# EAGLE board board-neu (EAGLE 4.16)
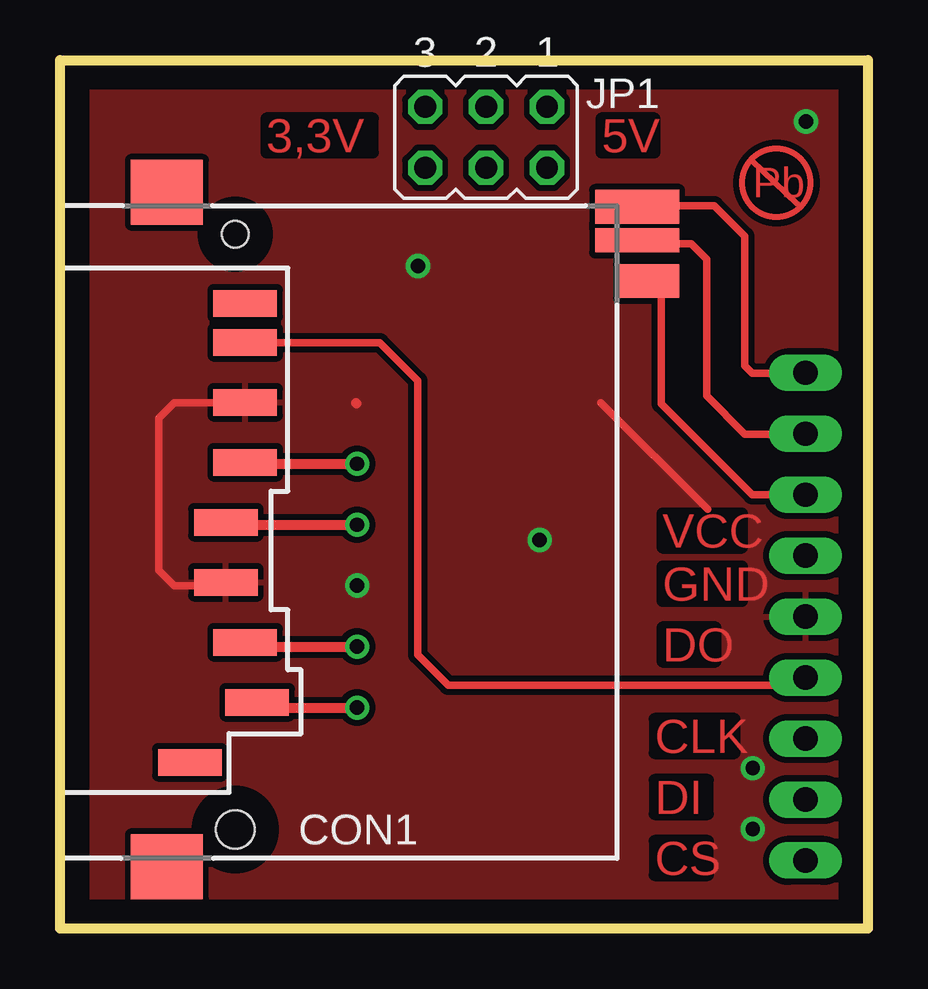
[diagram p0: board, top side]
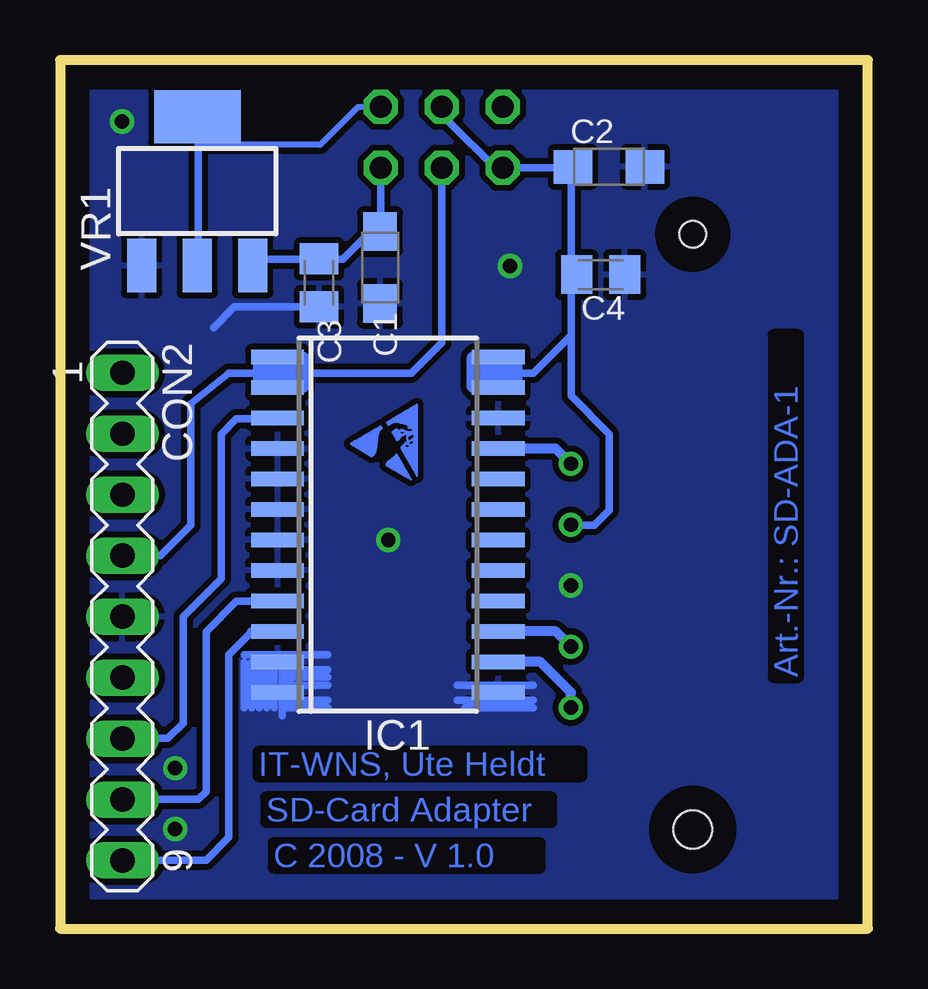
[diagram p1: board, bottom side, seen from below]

Size 33.66 x 36.19 mm. Coordinates in mm from the lower left corner, seen from the top.
Outline: 0,0 0,36.19 33.66,36.19 33.66,0 0,0
Copper layers (1*16): Top 0.035mm / dielectric 1.5mm / Bottom 0.035mm
Design rules "default": minimum track width 10mil, minimum drill 24mil, track to track 8mil, track to pad 8mil, pad to pad 8mil, via to via 8mil, smd to smd 8mil, copper to edge 40mil, drill to drill 8mil, minimum pad ring 10mil, minimum via ring 8mil, stop-mask expansion 4mil, vias tented up to drill 0mil, thermal gap 10mil
Milling: 4 lines

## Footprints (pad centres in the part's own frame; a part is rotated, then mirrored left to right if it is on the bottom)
SMC_A = smd 1.6 x 1.4: + -1.5,0; - 1.5,0
C0805K = smd 1.3 x 1.6: 1 -1,0; 2 1,0
FPS009-3000 = smd 2.65 x 1.1: 1 -0.915,-5.3; 2 -0.415,-7.8; 3 0.385,-10.3; 4 0.385,-12.8; 5 -0.415,-15.3; 6 -0.415,-17.8; 7 -0.415,-20.3; 8 -0.415,-21.925; 9 1.885,-2.8 | smd 3.5 x 1: COM_TERM -16.75,-24.55 | smd 2.5 x 1.4: DETECT -17.25,-22.85 | smd 3 x 2.7: M1 2.85,1.55; M2 2.85,-26.55 | smd 3.5 x 1.4: WRITE_PROT -16.75,-25.95 | hole 1.6: 0,0 | hole 1.1: 0,-24.8
MA09-1 = drill 1.016 long: 1 -10.16,0; 2 -7.62,0; 3 -5.08,0; 4 -2.54,0; 5 0,0; 6 2.54,0; 7 5.08,0; 8 7.62,0; 9 10.16,0
SO24 = smd 0.6 x 2.2: 1 -6.985,-4.6; 2 -5.715,-4.6; 3 -4.445,-4.6; 4 -3.175,-4.6; 5 -1.905,-4.6; 6 -0.635,-4.6; 7 0.635,-4.6; 8 1.905,-4.6; 9 3.175,-4.6; 10 4.445,-4.6; 11 5.715,-4.6; 12 6.985,-4.6; 13 6.985,4.6; 14 5.715,4.6; 15 4.445,4.6; 16 3.175,4.6; 17 1.905,4.6; 18 0.635,4.6; 19 -0.635,4.6; 20 -1.905,4.6; 21 -3.175,4.6; 22 -4.445,4.6; 23 -5.715,4.6; 24 -6.985,4.6
JP3Q = drill 0.914 octagon: 1 -2.54,-1.27; 2 -2.54,1.27; 3 0,-1.27; 4 0,1.27; 5 2.54,-1.27; 6 2.54,1.27
SOT-233 = smd 1.219 x 2.235: 1 -2.311,-3.099; 2 0,-3.099; 3 2.311,-3.099 | smd 3.6 x 2.2: 4 0,3.099

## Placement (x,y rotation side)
C1  10µF  [SMC_A]  20.33,27.54 270 bottom
C2  10µF  [SMC_A]  10.79,31.74 0 bottom
C3  100nF  [C0805K]  22.87,26.91 270 bottom
C4  100nF  [C0805K]  11.13,27.25 180 bottom
CON1  [FPS009-3000]  7.3,4.13 180 top
CON2  [MA09-1]  31.07,13 270 bottom
E$2  [GEH1]  21.88,22.15 270 top
IC1  74LVC4245  [SO24]  20,16.83 270 bottom
JP1  [JP3Q]  17.75,32.97 180 top
VR1  LM1117-3.3  [SOT-233]  27.94,30.73 0 bottom

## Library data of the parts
C1-C4 = rcl
CON1 = con-yamaichi
CON2 = con-lstb
E$2 = layout_s65
IC1 = micro-philips
JP1 = jumper
VR1 = LM1117

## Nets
GND: C1.- C2.- C3.2 C4.1 CON1.3 CON1.6 CON2.5 IC1.4 IC1.5 IC1.6 IC1.7 IC1.8 IC1.11 IC1.12 IC1.13 IC1.22 VR1.1

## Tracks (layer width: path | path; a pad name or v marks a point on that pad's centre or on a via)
GND  (via drill 0.6)
  Top 0.305: 6.66,21.91 4.76,21.91 4.12,21.27 4.12,14.92 4.76,14.29 6.03,14.29 | 26.98,17.46 22.54,21.91
  Top 0.406: 12.36,21.87 12.33,21.91
  Bottom 0.305: 13.95,9.19 16.8,9.19 | 13.95,10.14 17.12,10.14 | 15.22,9.51 15.85,9.51 | 15.22,9.51 13.95,9.51 | 15.22,9.51 17.12,9.51 | 24.41,10.78 24.41,11.1 | 24.41,10.78 22.51,10.78 | 24.41,10.46 24.41,10.78 | 24.41,10.46 22.51,10.46 | 24.41,10.14 24.41,10.46 | 24.41,10.14 22.51,10.14 | 24.41,9.51 24.41,10.14 | 24.41,9.51 22.51,9.51 | 24.41,9.19 24.41,8.88 | 24.41,9.19 24.41,9.51 | 22.51,9.19 24.41,9.19 | 22.51,11.41 25.99,11.41 | 24.09,9.19 24.09,11.1 | 24.73,9.19 24.73,11.1 | 25.04,9.19 25.04,11.1 | 25.36,9.19 25.36,11.1 | 25.99,9.19 25.99,11.1 | 25.68,9.19 25.68,11.1 | C3.2 26.39,25.91 27.26,25.04
  other vias: 12.38,14.29 19.99,16.19 14.91,27.61 31.08,33.63 28.86,6.68 28.86,4.15
  pour Top (isolate 0.254): 0.95,-0.32 0.63,36.19 33.66,35.87 33.66,-0.64
  pour Bottom (isolate 0.254): 0.31,36.19 0,-0.01 33.67,-0.01 33.66,36.19
S$1
  Top 0.305: 7.92,24.41 13.31,24.41 14.9,22.82 14.9,11.41 16.17,10.14 31.07,10.14
S$2
  Top 0.305: 25.04,26.63 25.04,21.87 28.85,18.07 31.07,18.07
S$3
  Bottom 0.305: 25.08,13.65 25.71,13.65
S$4
  Bottom 0.305: 23.49,22.54 23.46,22.51 23.77,22.51 23.81,22.54 23.84,22.51 24.09,22.51 24.13,22.54 | 24.13,23.81 24.16,23.77 24.41,23.77 24.41,23.78 24.44,23.81
  Bottom 0.406: 23.49,22.54 23.49,23.81 | 23.81,22.54 23.81,23.81 | 24.13,23.81 24.13,22.54 | 24.44,22.54 24.44,23.81 24.76,23.81 | 24.76,23.81 24.76,22.54 | 25.08,23.81 24.76,23.81 | 25.08,23.81 25.08,22.54 | 25.08,23.81 25.39,23.81 25.39,22.54
S$5
  Top 0.305: 25.36,28.53 26.31,28.53 26.95,27.9 26.95,22.19 28.53,20.61 31.07,20.61
S$6
  Top 0.305: 25.04,30.11 27.26,30.11 28.53,28.85 28.53,23.46 28.85,23.14 31.07,23.14
S$7  (via drill 0.6)
  Top 0.406: 8.57,19.37 v12.38,19.37
  Bottom 0.406: 15.55,20 13.01,20 v12.38,19.37
S$8  (via drill 0.6)
  Top 0.406: 7.3,16.83 v12.38,16.83
  Bottom 0.406: 12.36,16.8 12.36,16.81 v12.38,16.83
S$9
  Bottom 0.305: 25.68,12.36 26.63,11.41 26.63,3.8 27.58,2.85 29.8,2.85 30.75,2.85 31.07,2.85
S$10  (via drill 0.6)
  Top 0.406: 8.57,9.21 v12.38,9.21
  Bottom 0.406: 14.92,11.11 13.65,11.11 12.38,9.84 v12.38,9.21
S$14
  Bottom 0.305: 25.04,13.63 26.31,13.63 27.58,12.36 27.58,5.71 27.9,5.39 31.07,5.39
S$15
  Top 0.254: 30.73,30.19 28.82,32
S$16
  Bottom 0.305: 25.68,21.24 26.31,21.24 26.95,20.61 26.95,14.58 28.53,13 28.53,8.56 29.16,7.92 31.07,7.92
S$17
  Bottom 0.305: 31.07,15.53 29.48,15.53 28.21,16.8 28.21,21.87 26.63,23.14 25.04,23.14
S$18
  Bottom 0.305: 15.87,22.54 15.91,22.51 16.17,22.51 16.17,22.52 16.19,22.54 16.22,22.51 16.48,22.51 16.48,22.52 16.5,22.54 | 15.55,23.81 15.59,23.77 15.87,23.77
  Bottom 0.406: 15.55,22.54 15.55,23.81 15.24,23.81 | 14.92,23.81 14.6,23.81 14.6,22.54 | 14.92,23.81 15.24,23.81 | 15.24,23.81 15.24,22.54 | 14.92,22.54 14.92,23.81 | 15.87,22.54 15.87,23.77 15.87,23.81 | 16.19,22.54 16.19,23.81 | 16.5,22.54 16.5,23.81
S$19
  Bottom 0.305: 15.22,23.14 13.95,23.14 12.36,24.73 | 15.22,31.7 12.36,31.7 12.36,25.04 | 12.36,25.04 12.36,24.73 | 12.36,24.73 12.36,24.41 | 12.36,25.04 12.36,22.19 10.78,20.61 10.78,17.43 11.41,16.8 12.68,16.8
S$20
  Bottom 0.305: 25.08,12.38 25.71,12.38
S$21
  Bottom 0.305: 20.29,31.7 20.29,29.48 21.87,27.9 25.36,27.9
S$22
  Bottom 0.254: 27.26,32.97 27.9,32.65 22.82,32.65 21.24,34.24 20.61,34.24
  Bottom 0.305: 27.9,32.65 27.9,27.9
S$23
  Bottom 0.305: 17.75,31.7 17.75,24.41 19.02,23.14 24.73,23.14
S$24  (via drill 0.6)
  Top 0.406: 8.57,11.75 v12.38,11.75
  Bottom 0.406: 14.92,12.38 13.01,12.38 v12.38,11.75
S$25
  Bottom 0.305: 17.43,34.24 17.43,33.6 15.53,31.7
(copper drawn outside any net)
  shapes: Top circle x1

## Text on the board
Top: 3,3V | 5V | Pb | VCC | GND | DO | CLK | DI | CS
Bottom: Art.-Nr.: SD-ADA-1 | IT-WNS, Ute Heldt | SD-Card Adapter | C 2008 - V 1.0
